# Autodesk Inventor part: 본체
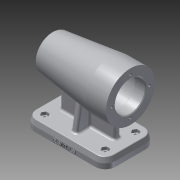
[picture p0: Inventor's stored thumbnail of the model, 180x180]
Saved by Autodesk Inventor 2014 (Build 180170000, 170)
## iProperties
Created: 2017-01
Part Number: 본체
Material: Aluminum 6061
Document SubType Name: Modeling
Designer: user
Density: 2.71 g/cm^3
Appearance: Aluminum - Flat
Mass: 797.096 g
Surface Area: 656.654 cm^2
Volume: 294.131 cm^3
Author: user
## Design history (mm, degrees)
sketch "Sketch1"
  geometry: L1 (-42, 35)-(42, 35); L2 (56, 21)-(56, -21); L3 (42, -35)-(-42, -35); L4 (-56, -21)-(-56, 21); L5 (-56, 35)-(56, -35); L6 (56, 35)-(-56, -35); A1 r 14 centre (-42, 21) between (-42, 35) and (-56, 21); A2 r 14 centre (-42, -21) between (-56, -21) and (-42, -35); A3 r 14 centre (42, -21) between (42, -35) and (56, -21); A4 r 14 centre (42, 21) between (56, 21) and (42, 35); 1 further point
  constraints: 12 end point, 8 point on circle, 8 point on line, 8 tangent, 4 centre point, 3 equal radius, 2 midpoint, 2 parallel, 1 horizontal, 1 perpendicular
  dimensions: "d0" = 112 distance of L5.end L6.end; "d1" = 70 distance of L6.start L5.end; "d2" = 14 radius of A1
extrude "Extrusion1" new body sketch "Sketch1" distance "d3" = 7; taper "d4" = 0 deg
sketch "Sketch2"
  geometry: L1 (56, -21)-(56, 21) reference; L2 (42, 35)-(-42, 35) reference; L3 (-56, 21)-(-56, -21) reference; L4 (-42, -35)-(42, -35) reference; A1 r 14 centre (42, 21) between (56, 21) and (42, 35) reference; A2 r 14 centre (-42, 21) between (-42, 35) and (-56, 21) reference; A3 r 14 centre (-42, -21) between (-56, -21) and (-42, -35) reference; A4 r 14 centre (42, -21) between (42, -35) and (56, -21) reference; 1 further point
extrude "Extrusion2" join sketch "Sketch2" distance "d5" = 7; taper "d6" = -15 deg
workplane "Work Plane1"
sketch "Sketch4"
  geometry: L1 (98, 0)-(98, 7) reference; L2 (98, 40)-(98, 108) reference; L3 (98, 108)-(70, 108); L4 (70, 108)-(184.9, 108); L5 (98, 74)-(-14, 74); L6 (70, 108)-(-10.27, 98.144); L7 (-14, 74)-(-14, 74.122); L8 (98, 0)-(84, 0) reference; A1 r 80 centre (66, 74) between (-10.27, 98.144) and (-14, 74); 1 further point
  constraints: 12 end point, 2 perpendicular, 2 point on circle, 1 centre point, 1 collinear, 1 horizontal, 1 midpoint, 1 point on line, 1 tangent, 1 vertical
  dimensions: "d7" = 68 distance of L2.start L2.end; "d8" = 28 distance of L2.end L3.end; "d11" = 160 diameter of A1; "d14" = 74 distance from line of L8 L5.start
revolve "Revolution1" sketch "Sketch4" stored, may be unused: angle "d12" = 90 deg
fillet "Fillet1" dims "d13" = 3
sketch "Sketch5"
  geometry: L1 (42, -33.124)-(-42, -33.124) reference; L2 (-4, 23)-(4, 23); L3 (4, 23)-(4, 4); L4 (4, 4)-(38, 4); L5 (38, 4)-(38, -4); L6 (38, -4)-(4, -4); L7 (4, -4)-(4, -23); L8 (4, -23)-(-4, -23); L9 (-4, -23)-(-4, -4); L10 (-4, -4)-(-38, -4); L11 (-38, -4)-(-38, 4); L12 (-38, 4)-(-4, 4); L13 (-4, 4)-(-4, 23); L14 (56, -21)-(56, 21) reference; L15 (42, 35)-(-42, 35) reference; L16 (-56, 21)-(-56, -21) reference; L17 (-42, -35)-(42, -35) reference; 1 further point
  constraints: 24 end point, 9 parallel, 3 perpendicular
  dimensions: "d15" = 8 distance of L2.start L2.end; "d16" = 8 distance of L4.end L5.end; "d17" = 8 distance of L7.end L8.end; "d18" = 8 distance of L10.end L11.end; "d19" = 52 distance from line of L14 L2.end; "d20" = 31 distance between parallel lines of L15 L4; "d21" = 31 distance between parallel lines of L15 L12; "d22" = 52 distance between parallel lines of L14 L7; "d23" = 18 distance between parallel lines of L16 L11; "d24" = 18 distance between parallel lines of L14 L5; "d25" = 12 distance between parallel lines of L15 L2; "d26" = 12 distance between parallel lines of L17 L8
extrude "Extrusion3" join sketch "Sketch5" stored distance "d27" = 7; taper "d28" = 0 deg
feature "FaceDraft1" dims angle "d29" = 10 deg
feature "FaceDraft2" dims angle "d30" = 10 deg
hole "Hole1" diameter "d33" = 21; stored, may be unused: countersink angle "d37" = 82 deg, drill point angle "d39" = 0 deg; dims "d34" = 19.05, "d35" = 9.525, "d36" = 6.35, "d38" = 106, "d40" = 25.4, "d41" = 25.4
hole "Hole2" diameter "d44" = 32; stored, may be unused: countersink angle "d48" = 82 deg, drill point angle "d50" = 0 deg; dims "d45" = 19.05, "d46" = 9.525, "d47" = 6.35, "d49" = 103, "d51" = 25.4, "d52" = 25.4
hole "Hole3" diameter "d55" = 35; stored, may be unused: countersink angle "d59" = 82 deg, drill point angle "d61" = 0 deg; dims "d56" = 19.05, "d57" = 9.525, "d58" = 6.35, "d60" = 99, "d62" = 25.4, "d63" = 25.4
hole "Hole4" diameter "d66" = 42; stored, may be unused: countersink angle "d70" = 82 deg, drill point angle "d72" = 0 deg; dims "d67" = 19.05, "d68" = 9.525, "d69" = 6.35, "d71" = 81, "d73" = 25.4, "d74" = 25.4
workplane "Work Plane2"
sketch "Sketch6"
  geometry: C1 r 21 at (0, 0) reference; C2 r 24 at (0, 0); 1 further point
  constraints: 1 centre point, 1 coincident
  dimensions: "d76" = 48 diameter of C2
extrude "Extrusion4" cut sketch "Sketch6" distance "d77" = 54; taper "d78" = 0 deg
fillet "Fillet2" dims "d79" = 0.3
chamfer "Chamfer1" distance "d81" = 1; stored, may be unused: second distance "d82" = 3.175, angle "d83" = 45 deg
fillet "Fillet4" dims "d84" = 3
fillet "Fillet5" dims "d85" = 3
fillet "Fillet6" dims "d86" = 1
sketch "Sketch7"
  geometry: C1 r 2.5 at (-42, 21); A1 r 11.357 centre (-42, 21) between (-42, 32.357) and (-53.357, 21) reference; 1 further point
  constraints: 1 centre point, 1 coincident
  dimensions: "d87" = 5 diameter of C1
extrude "Extrusion5" cut sketch "Sketch7" distance "d88" = 54; taper "d89" = 0 deg
sketch "Sketch8" dims "d90" = 10
  geometry: L1 (-39.51, 25.336)-(-37, 21.012); L2 (-37, 21.012)-(-39.49, 16.676); L3 (-39.49, 16.676)-(-44.49, 16.664); L4 (-44.49, 16.664)-(-47, 20.988); L5 (-47, 20.988)-(-44.51, 25.324); L6 (-44.51, 25.324)-(-39.51, 25.336); A1 r 11.357 centre (-42, 21) between (-42, 32.357) and (-53.357, 21) reference; 3 further points
  constraints: 12 end point, 2 coincident, 16 other
extrude "Extrusion6" cut sketch "Sketch8" distance "d91" = 4; taper "d92" = 0 deg
mirror "Mirror1"
sketch "Sketch9"
  geometry: L1 (0, 0)-(84, 0) reference; L2 (26.07, 6.019)-(57.791, 6.019); L3 (57.791, 6.019)-(57.791, 1.53); L4 (57.791, 1.53)-(26.07, 1.53); L5 (26.07, 1.53)-(26.07, 6.019); 2 further points
  constraints: 2 other
  dimensions: "d93" = 4 distance from line of L1 point (42, 4)
emboss "Emboss1" sketch "Sketch9" dims "d0" = 112, "d1" = 70, "d2" = 14, "d94" = 0.5, "d95" = 0
sketch "Sketch10" dims "d96" = 52
  geometry: L1 (0, 0)-(0, 26); C1 r 22 at (0, 0) reference; 1 further point
  constraints: 2 end point, 1 coincident, 1 vertical, 1 vertical alignment, 2 other
hole "Hole5" sketch "Sketch10" at (0, 26) diameter "d97" = 3.2512; stored, may be unused: countersink angle "d101" = 82 deg, drill point angle "d103" = 118 deg; dims "d98" = 8, "d99" = 9.525, "d100" = 6.35, "d102" = 11
pattern_circular "Circular Pattern1" dims angle "d105" = 360 deg
workplane "Work Plane4"
mirror "Mirror3"
fillet "Fillet7" dims "d107" = 3
body "Solid1"
other parameters: "d9" = 112, "d10" = 173 deg, "d75" = -15
